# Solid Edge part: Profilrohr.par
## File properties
Username: bmolnar
Dokumentum tartalom típus: 0
Author: bmolnar
Last saved by: bmolnar
Revision: 77
Sűrűség: 0,000 kg/m^3
Pontosság: 0,990
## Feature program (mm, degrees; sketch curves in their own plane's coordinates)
base feature "unnamed BaseFeature 1"
thread "unnamed Thread 1"
thread "Menet_2"  ThreadDepth = 7.5 mm
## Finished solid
Body 1: solid body, 121 faces, 264 edges, 192 vertices.
  Faces by surface: plane 78, cylinder 29, cone 10, torus 4
  Edges by curve: line 188, circle 68, curve on surface 8
Bounding box of the edges (mm; curved faces can reach further): 65.000 x 70.000 x 49.500, from (-32.5, -32.5, 0) to (32.5, 37.5, 49.5).
Cylindrical faces by radius (mm): R1.375 x2, R3.4 x4, R4.283 x4, R5.5 x8, R25 x1, R25.9 x2, R26.1 x2, R27.6 x2, R43 x4
Conical faces (half-angle, radius in mm at the cone's reference point): 30 deg R25.325 x2, 30 deg R26.1887 x2, 45 deg R4.533 x2, 45 deg R26.25 x2, 45 deg R26.35 x2
Toroidal faces (ring radius, tube radius in mm): R27.4 r0.2 x4
Planar faces by outward normal: +x 9, +y 11, +z 8, -x 9, -y 9, -z 8, oblique 24
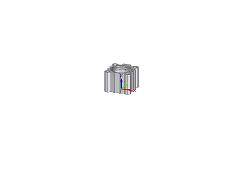
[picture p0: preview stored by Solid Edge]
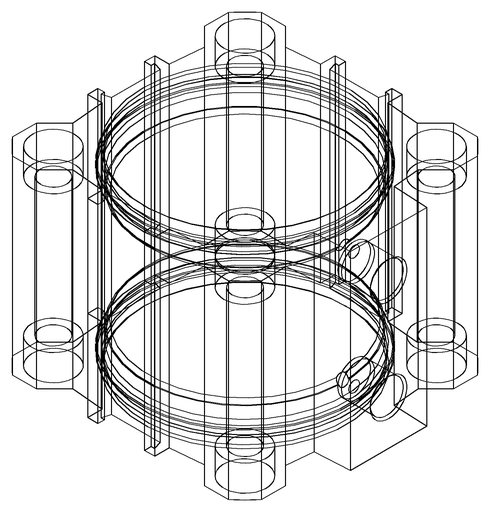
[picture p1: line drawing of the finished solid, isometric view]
